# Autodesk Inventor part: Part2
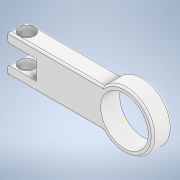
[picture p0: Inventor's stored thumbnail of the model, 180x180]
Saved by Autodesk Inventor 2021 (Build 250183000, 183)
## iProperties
Created: 2025-05
Part Number: Part2
Material: Generic
Document SubType Name: Modeling
Designer: Aaditya
Density: 1 g/cm^3
Appearance: Default
Author: Aaditya
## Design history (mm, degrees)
sketch "Sketch1"
  geometry: C1 r 150 at (0, 0); 1 further point
  constraints: 1 centre point, 1 coincident
  dimensions: "d0" = 300 diameter of C1
extrude "Extrusion1" new body sketch "Sketch1" distance "d1" = 100; taper "d2" = 0 deg
sketch "Sketch2"
  geometry: L1 (-611.803, 100)-(-111.803, 100); L2 (-111.803, 100)-(-111.803, -100); L3 (-111.803, -100)-(-611.803, -100); L4 (-611.803, -100)-(-611.803, 100); 3 further points
  constraints: 8 end point, 2 parallel, 1 horizontal, 1 perpendicular, 2 other
  dimensions: "d3" = 200 distance of L3.end L1.start; "d4" = 500 distance of L1.start L1.end; "d5" = 100 distance from line of point (0, 0) L1
extrude "Extrusion2" join sketch "Sketch2" distance "d6" = 100; taper "d7" = 0 deg
sketch "Sketch3"
  geometry: C1 r 125 at (0, 0); 1 further point
  constraints: 1 centre point, 1 coincident
  dimensions: "d8" = 250 diameter of C1
extrude "Extrusion3" cut sketch "Sketch3" extent not by distance; stored distance "d9" = 0; taper "d10" = 0 deg
sketch "Sketch4"
  geometry: 1 further point
sketch "Sketch5"
  geometry: L1 (500, -100)-(0, -100) reference; L2 (0, 0)-(0, -100) reference; C1 r 40 at (50, -50); 1 further point
  constraints: 1 centre point
  dimensions: "d11" = 80 diameter of C1; "d12" = 50 distance from line of L1 C1.centre; "d13" = 50 distance from line of L2 C1.centre
extrude "Extrusion4" cut sketch "Sketch5" extent not by distance; stored distance "d14" = 0; taper "d15" = 0 deg
sketch "Sketch6"
  geometry: 1 further point
sketch "Sketch7"
  geometry: L1 (-611.803, -100)-(-611.803, 100) reference; L2 (-611.803, 50)-(-461.803, 50); L3 (-461.803, 50)-(-461.803, -50); L4 (-461.803, -50)-(-611.803, -50); L5 (-611.803, -50)-(-611.803, 50); 2 further points
  constraints: 8 end point, 2 parallel, 1 horizontal, 1 perpendicular, 1 point on line
  dimensions: "d16" = 150 distance of L2.start L2.end; "d17" = 100 distance of L2.end L3.end; "d18" = 50 distance from line of point (0, 0) L2
extrude "Extrusion5" cut sketch "Sketch7" extent not by distance; stored distance "d19" = 0; taper "d20" = 0 deg
fillet "Fillet1" dims "d21" = 10
body "Solid1"
